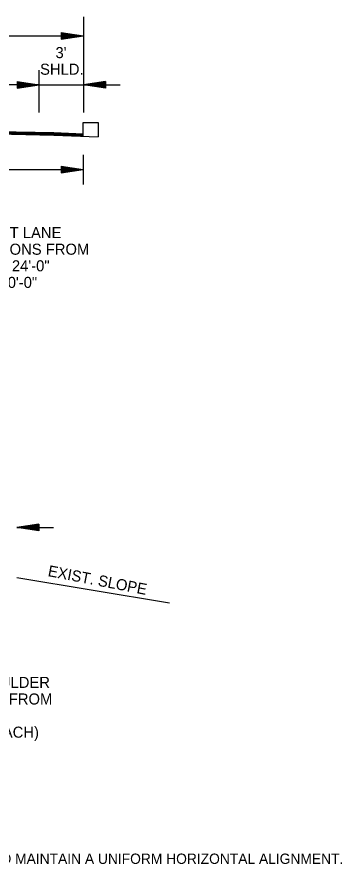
# Model space of a CAD drawing. Extents: x 542112 to 1930787, y -1968972 to 596640.
# Drawn here: x 545428 to 545649, y -1951935 to -1951361 of the extents above; entities that cross this region are included whole.
import ezdxf

# ---------------------------------------------------------------- set-up
doc = ezdxf.new("R2010")
doc.units = 0
for name, color, linetype in [('R_Border', 7, 'Continuous'), ('R_Border Notes', 7, 'Continuous'), ('R_Draft', 7, 'Continuous')]:
    doc.layers.add(name, color=color, linetype=linetype)

msp = doc.modelspace()

# ---------------------------------------------------------------- linework, layer by layer
at = {"layer": 'R_Border'}
for p, q in [((545473.31, -1951441.9), (545473.31, -1951432.49)), ((545473.31, -1951432.49), (545483.47, -1951432.49)), ((545483.47, -1951432.49), (545483.47, -1951442.31))]:
    msp.add_line(p, q, dxfattribs=at)
at = {"layer": 'R_Draft'}
for p, q in [((545473.38, -1951360.97), (545473.38, -1951425.69)), ((545073.38, -1951373.73), (545473.38, -1951373.73)), ((545458.38, -1951371.48), (545473.38, -1951373.73)), ((545458.38, -1951371.48), (545458.38, -1951375.98)), ((545458.38, -1951371.86), (545470.87, -1951373.73)), ((545458.38, -1951372.24), (545468.29, -1951373.73)), ((545458.38, -1951372.61), (545465.8, -1951373.73)), ((545458.38, -1951373), (545463.25, -1951373.73)), ((545458.38, -1951373.38), (545460.75, -1951373.73)), ((545458.38, -1951375.98), (545473.38, -1951373.73)), ((545458.38, -1951374.47), (545463.25, -1951373.73)), ((545458.38, -1951375.22), (545468.29, -1951373.73)), ((545458.38, -1951375.61), (545470.87, -1951373.73)), ((545458.38, -1951374.85), (545465.8, -1951373.73)), ((545458.38, -1951374.08), (545460.75, -1951373.73)), ((545443.38, -1951425.69), (545443.38, -1951397.13)), ((545428.38, -1951404.78), (545443.38, -1951407.03)), ((545428.38, -1951404.78), (545428.38, -1951409.28)), ((545428.38, -1951405.15), (545440.87, -1951407.03)), ((545428.38, -1951405.53), (545438.29, -1951407.03)), ((545488.38, -1951404.78), (545473.38, -1951407.03)), ((545488.38, -1951405.15), (545475.88, -1951407.03)), ((545488.38, -1951405.53), (545478.46, -1951407.03)), ((545488.38, -1951404.78), (545488.38, -1951409.28)), ((545443.38, -1951407.03), (545213.38, -1951407.03)), ((545428.38, -1951405.91), (545435.8, -1951407.03)), ((545428.38, -1951406.3), (545433.25, -1951407.03)), ((545428.38, -1951406.67), (545430.75, -1951407.03)), ((545428.38, -1951409.28), (545443.38, -1951407.03)), ((545428.38, -1951407.76), (545433.25, -1951407.03)), ((545428.38, -1951408.52), (545438.29, -1951407.03)), ((545428.38, -1951408.9), (545440.87, -1951407.03)), ((545428.38, -1951408.14), (545435.8, -1951407.03)), ((545428.38, -1951407.38), (545430.75, -1951407.03)), ((545443.38, -1951407.03), (545498.38, -1951407.03)), ((545488.38, -1951409.28), (545473.38, -1951407.03)), ((545488.38, -1951408.9), (545475.88, -1951407.03)), ((545488.38, -1951408.52), (545478.46, -1951407.03)), ((545488.38, -1951405.91), (545480.96, -1951407.03)), ((545488.38, -1951408.14), (545480.96, -1951407.03)), ((545488.38, -1951406.3), (545483.5, -1951407.03)), ((545488.38, -1951407.76), (545483.5, -1951407.03)), ((545488.38, -1951406.67), (545486.01, -1951407.03)), ((545488.38, -1951407.38), (545486.01, -1951407.03)), ((545213.38, -1951434.63), (545453.31, -1951439.43)), ((545213.38, -1951434.93), (545453.31, -1951439.73)), ((545213.38, -1951435.23), (545453.31, -1951440.03)), ((545213.38, -1951435.53), (545453.31, -1951440.33)), ((545213.38, -1951435.83), (545453.31, -1951440.63)), ((545213.38, -1951436.13), (545453.31, -1951440.93)), ((545213.38, -1951436.3), (545453.31, -1951441.1)), ((545453.29, -1951440.03), (545473.31, -1951440.83)), ((545453.3, -1951439.73), (545473.31, -1951440.53)), ((545453.31, -1951439.43), (545473.31, -1951440.23)), ((545453.24, -1951441.1), (545483.47, -1951442.31)), ((545453.26, -1951440.93), (545473.31, -1951441.73)), ((545453.27, -1951440.63), (545473.31, -1951441.43)), ((545453.28, -1951440.33), (545473.31, -1951441.13)), ((545473.31, -1951454.57), (545473.31, -1951474.57)), ((545458.31, -1951462.24), (545473.31, -1951464.49)), ((545458.31, -1951462.24), (545458.31, -1951466.74)), ((545458.31, -1951462.62), (545470.8, -1951464.49)), ((545458.31, -1951463), (545468.22, -1951464.49)), ((545073.38, -1951464.49), (545473.31, -1951464.49)), ((545458.31, -1951463.37), (545465.72, -1951464.49)), ((545458.31, -1951463.76), (545463.18, -1951464.49)), ((545458.31, -1951464.14), (545460.68, -1951464.49)), ((545458.31, -1951466.74), (545473.31, -1951464.49)), ((545458.31, -1951465.23), (545463.18, -1951464.49)), ((545458.31, -1951465.98), (545468.22, -1951464.49)), ((545458.31, -1951466.37), (545470.8, -1951464.49)), ((545458.31, -1951465.61), (545465.72, -1951464.49)), ((545458.31, -1951464.84), (545460.68, -1951464.49)), ((545443.18, -1951704.95), (545428.18, -1951707.2)), ((545443.18, -1951709.45), (545428.18, -1951707.2)), ((545428.18, -1951707.2), (545453.18, -1951707.2)), ((545443.18, -1951705.32), (545430.68, -1951707.2)), ((545443.18, -1951709.07), (545430.68, -1951707.2)), ((545443.18, -1951705.7), (545433.26, -1951707.2)), ((545443.18, -1951708.69), (545433.26, -1951707.2)), ((545443.18, -1951706.08), (545435.76, -1951707.2)), ((545443.18, -1951708.31), (545435.76, -1951707.2)), ((545443.18, -1951706.47), (545438.3, -1951707.2)), ((545443.18, -1951707.93), (545438.3, -1951707.2)), ((545443.18, -1951706.84), (545440.81, -1951707.2)), ((545443.18, -1951707.55), (545440.81, -1951707.2)), ((545443.18, -1951704.95), (545443.18, -1951709.45)), ((545428.18, -1951740.93), (545531.86, -1951758.21))]:
    msp.add_line(p, q, dxfattribs=at)

# ---------------------------------------------------------------- texts
at = {"layer": 'R_Border Notes'}
msp.add_text('STRINGLINE WILL BE USED TO MAINTAIN A UNIFORM HORIZONTAL ALIGNMENT.', height=7, dxfattribs=at).set_placement((545284.54, -1951935.23))
at = {"layer": 'R_Draft'}
for s, p in [("3' ", (545454.42, -1951388.91)), ('SHLD.', (545443.97, -1951400.16)), ('*RIGHT LANE', (545394.38, -1951510.96)), ('TRANSITIONS FROM ', (545377.61, -1951522.21)), ('22\'-0" TO 24\'-0"', (545379.83, -1951533.46)), ('IN 90\'-0"', (545403.63, -1951544.71)), ('***RIGHT SHOULDER', (545349.26, -1951815.91)), ('TRANSITIONS FROM ', (545352.54, -1951827.16)), ('36\'-6\'" (APPROACH)', (545350, -1951849.66))]:
    msp.add_text(s, height=7.5, dxfattribs=at).set_placement(p)
msp.add_text('EXIST. SLOPE', height=7.5, rotation=349.11714, dxfattribs=at).set_placement((545448.86, -1951740.03))

doc.saveas('drawing.dxf')
